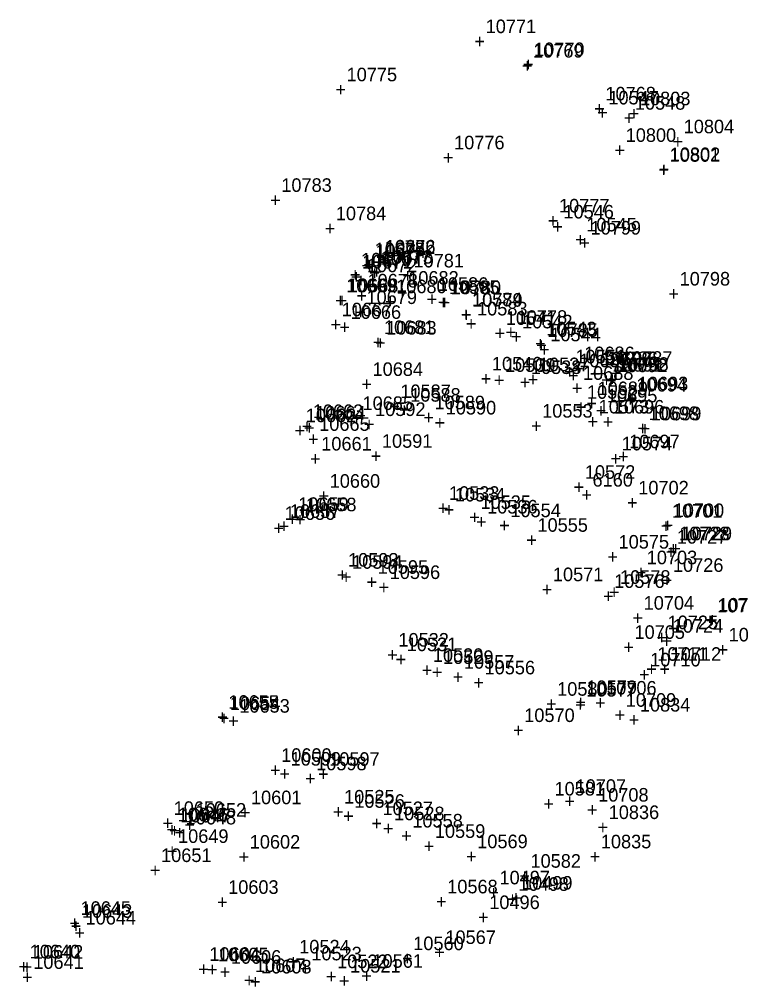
# Model space of a CAD drawing. Extents: x 1136220 to 1137808, y 528804 to 531215.
# Drawn here: x 1136954.1 to 1137087, y 530383.4 to 530561.6 of the extents above; entities that cross this region are included whole.
import ezdxf

# ---------------------------------------------------------------- set-up
doc = ezdxf.new("R2010")
doc.units = 0
for name, color, linetype in [('S_Buildings', 7, 'Continuous'), ('S_Buildings_SillElevation', 7, 'Continuous'), ('S_Curb_Type_1', 7, 'Continuous'), ('S_Curb_Type_3', 7, 'Continuous'), ('S_Drainage_CB', 7, 'Continuous'), ('S_Fencing_ChainLink', 7, 'Continuous'), ('S_Fencing_PostAndRail', 7, 'Continuous'), ('S_Ground_Elevation', 7, 'Continuous'), ('S_Property_IronPipeFound', 7, 'Continuous'), ('S_Property_Light', 7, 'Continuous'), ('S_Railroad_Tracks', 7, 'Continuous'), ('S_RetWall_Top', 7, 'Continuous'), ('S_Roadway_Centerline', 7, 'Continuous'), ('S_Roadway_Drive_Paved', 7, 'Continuous'), ('S_Roadway_Edge_Pavement', 7, 'Continuous'), ('S_Roadway_Sidewalks', 7, 'Continuous'), ('S_Traffic_Post_Conc', 7, 'Continuous'), ('S_Trees_Decid_NonPay', 7, 'Continuous'), ('S_Trees_HedgeLine', 7, 'Continuous'), ('S_Utilities_Pole_Power', 7, 'Continuous')]:
    doc.layers.add(name, color=color, linetype=linetype)

msp = doc.modelspace()

# ---------------------------------------------------------------- texts
at = {"layer": 'S_Buildings'}
for s, p in [('10834', (1137068.47, 530434.07)), ('+', (1137066.41, 530431.32)), ('10835', (1137061.28, 530408.87)), ('+', (1137059.22, 530406.12))]:
    msp.add_text(s, height=2.5, dxfattribs=at).set_placement(p)
at = {"layer": 'S_Buildings_SillElevation'}
for s, p in [('10836', (1137062.73, 530414.27)), ('+', (1137060.67, 530411.52))]:
    msp.add_text(s, height=2.5, dxfattribs=at).set_placement(p)
at = {"layer": 'S_Curb_Type_1'}
for s, p in [('10770', (1137048.98, 530554.79)), ('+', (1137046.92, 530552.04)), ('10802', (1137073.99, 530535.45)), ('+', (1137071.93, 530532.7))]:
    msp.add_text(s, height=2.5, dxfattribs=at).set_placement(p)
at = {"layer": 'S_Curb_Type_3'}
for s, p in [('10674', (1137019.78, 530517.62)), ('10671', (1137017.29, 530515.66)), ('+', (1137017.72, 530514.87)), ('+', (1137015.23, 530512.91)), ('10668', (1137014.68, 530511.31)), ('+', (1137012.62, 530508.56)), ('10667', (1137013.53, 530506.87)), ('+', (1137011.47, 530504.12)), ('10690', (1137061.32, 530497.81)), ('10691', (1137063.41, 530496.67)), ('+', (1137059.26, 530495.06)), ('+', (1137061.35, 530493.92)), ('10694', (1137067.83, 530493.01)), ('+', (1137065.76, 530490.26)), ('10664', (1137008.63, 530487.85)), ('10698', (1137070.07, 530487.76)), ('+', (1137006.57, 530485.1)), ('+', (1137068.01, 530485.01)), ('10657', (1137003.99, 530469.74)), ('10701', (1137074.39, 530469.78)), ('+', (1137001.93, 530466.99)), ('+', (1137072.33, 530467.03)), ('10728', (1137075.7, 530465.61)), ('+', (1137073.64, 530462.86)), ('10731', (1137082.73, 530452.33)), ('+', (1137080.67, 530449.58)), ('10654', (1136992.94, 530434.34)), ('+', (1136990.88, 530431.59)), ('10647', (1136983.81, 530413.65)), ('+', (1136981.75, 530410.9)), ('10643', (1136965.67, 530396.08)), ('+', (1136963.61, 530393.33)), ('10642', (1136956.62, 530388.55)), ('+', (1136954.56, 530385.8))]:
    msp.add_text(s, height=2.5, dxfattribs=at).set_placement(p)
at = {"layer": 'S_Drainage_CB'}
for s, p in [('10771', (1137040.06, 530559.02)), ('+', (1137037.99, 530556.27)), ('10784', (1137012.45, 530524.57)), ('+', (1137010.39, 530521.82)), ('10787', (1137065.17, 530497.92)), ('+', (1137063.11, 530495.17)), ('10662', (1137006.91, 530487.36)), ('10592', (1137019.68, 530488.5)), ('+', (1137004.85, 530484.61)), ('+', (1137017.62, 530485.75)), ('10578', (1137064.82, 530457.59)), ('+', (1137062.76, 530454.84)), ('10650', (1136982.57, 530415.03)), ('+', (1136980.51, 530412.28))]:
    msp.add_text(s, height=2.5, dxfattribs=at).set_placement(p)
at = {"layer": 'S_Fencing_ChainLink'}
for s, p in [('10496', (1137040.73, 530397.69)), ('+', (1137038.67, 530394.94))]:
    msp.add_text(s, height=2.5, dxfattribs=at).set_placement(p)
at = {"layer": 'S_Fencing_PostAndRail'}
for s, p in [('10661', (1137009.77, 530482.14)), ('+', (1137007.71, 530479.39))]:
    msp.add_text(s, height=2.5, dxfattribs=at).set_placement(p)
at = {"layer": 'S_Ground_Elevation'}
for s, p in [('10673', (1137021.04, 530516.58)), ('10672', (1137018.17, 530514.99)), ('+', (1137018.98, 530513.83)), ('10682', (1137025.79, 530512.69)), ('+', (1137016.11, 530512.24)), ('10586', (1137031.23, 530511.55)), ('+', (1137023.73, 530509.94)), ('+', (1137029.17, 530508.8)), ('10583', (1137038.47, 530507.02)), ('10666', (1137015.18, 530506.39)), ('10541', (1137043.77, 530505.29)), ('10683', (1137021.73, 530503.49)), ('+', (1137036.41, 530504.27)), ('+', (1137013.12, 530503.64)), ('+', (1137041.7, 530502.54)), ('10544', (1137051.97, 530502.26)), ('+', (1137019.67, 530500.74)), ('+', (1137049.9, 530499.51)), ('10551', (1137056.6, 530498.19)), ('10540', (1137041.21, 530496.89)), ('10537', (1137049.87, 530496.75)), ('10684', (1137019.22, 530495.88)), ('+', (1137054.54, 530495.44)), ('+', (1137017.16, 530493.13)), ('+', (1137039.15, 530494.14)), ('+', (1137047.81, 530494)), ('10587', (1137024.34, 530491.8)), ('10552', (1137058.73, 530491.67)), ('10685', (1137017.38, 530489.61)), ('+', (1137022.28, 530489.05)), ('10590', (1137032.7, 530488.78)), ('10553', (1137050.47, 530488.2)), ('+', (1137056.67, 530488.92)), ('10573', (1137060.88, 530488.98)), ('10665', (1137009.39, 530485.77)), ('+', (1137015.32, 530486.86)), ('+', (1137030.64, 530486.03)), ('+', (1137058.82, 530486.23)), ('+', (1137048.41, 530485.45)), ('+', (1137007.33, 530483.02)), ('10574', (1137065.12, 530482.17)), ('+', (1137063.06, 530479.42)), ('10572', (1137058.33, 530476.93)), ('10533', (1137033.3, 530473.06)), ('+', (1137056.26, 530474.18)), ('10659', (1137005.52, 530471.02)), ('+', (1137031.24, 530470.31)), ('10536', (1137040.33, 530470.54)), ('10554', (1137044.61, 530469.87)), ('+', (1137003.45, 530468.27)), ('+', (1137038.27, 530467.79)), ('+', (1137042.55, 530467.12)), ('10555', (1137049.6, 530467.18)), ('+', (1137047.54, 530464.43)), ('10575', (1137064.55, 530464.08)), ('10593', (1137014.71, 530460.76)), ('+', (1137062.49, 530461.33)), ('+', (1137012.65, 530458.01)), ('10596', (1137022.38, 530458.48)), ('10571', (1137052.45, 530458.08)), ('+', (1137020.32, 530455.73)), ('10576', (1137063.73, 530456.84)), ('+', (1137050.39, 530455.33)), ('+', (1137061.67, 530454.1)), ('10532', (1137023.98, 530446.03)), ('+', (1137021.91, 530443.28)), ('10529', (1137032.21, 530442.84)), ('10557', (1137036.05, 530441.96)), ('+', (1137030.15, 530440.09)), ('10556', (1137039.86, 530440.92)), ('+', (1137033.99, 530439.21)), ('+', (1137037.8, 530438.17)), ('10577', (1137058.61, 530436.83)), ('10579', (1137058.64, 530437.3)), ('+', (1137056.58, 530434.55)), ('10570', (1137047.17, 530432.14)), ('+', (1137056.55, 530434.08)), ('+', (1137045.11, 530429.39)), ('10600', (1137002.38, 530424.8)), ('10597', (1137011.23, 530424.07)), ('+', (1137000.32, 530422.05)), ('+', (1137009.17, 530421.32)), ('10581', (1137052.74, 530418.6)), ('10525', (1137013.97, 530417.12)), ('+', (1137050.68, 530415.85)), ('10648', (1136984.77, 530413.28)), ('+', (1137011.91, 530414.37)), ('10528', (1137023.19, 530414.05)), ('10558', (1137026.55, 530412.71)), ('+', (1137021.13, 530411.3)), ('10559', (1137030.7, 530410.8)), ('+', (1136982.71, 530410.53)), ('+', (1137024.49, 530409.96)), ('+', (1137028.64, 530408.05)), ('10569', (1137038.51, 530408.9)), ('+', (1137036.45, 530406.15)), ('10582', (1137048.32, 530405.3)), ('+', (1137046.26, 530402.55)), ('10568', (1137032.98, 530400.58)), ('10499', (1137046.76, 530401.27)), ('+', (1137030.92, 530397.83)), ('+', (1137044.7, 530398.52)), ('10644', (1136966.33, 530394.84)), ('+', (1136964.27, 530392.09)), ('10567', (1137032.64, 530391.26)), ('10524', (1137005.71, 530389.51)), ('10560', (1137026.72, 530390.12)), ('10605', (1136990.76, 530388.07)), ('+', (1137030.58, 530388.51)), ('10641', (1136956.71, 530386.67)), ('10608', (1136998.68, 530385.83)), ('+', (1137003.65, 530386.76)), ('10521', (1137015.08, 530385.99)), ('10561', (1137019.2, 530386.88)), ('+', (1137024.66, 530387.37)), ('+', (1136988.7, 530385.32)), ('+', (1136954.65, 530383.92)), ('+', (1136996.62, 530383.08)), ('+', (1137013.02, 530383.24)), ('+', (1137017.14, 530384.13))]:
    msp.add_text(s, height=2.5, dxfattribs=at).set_placement(p)
at = {"layer": 'S_Property_IronPipeFound'}
for s, p in [('6160', (1137059.75, 530475.5)), ('+', (1137057.69, 530472.75))]:
    msp.add_text(s, height=2.5, dxfattribs=at).set_placement(p)
at = {"layer": 'S_Property_Light'}
for s, p in [('10591', (1137020.95, 530482.65)), ('+', (1137018.89, 530479.9)), ('10732', (1137084.83, 530446.98)), ('+', (1137082.77, 530444.23)), ('10580', (1137053.23, 530436.98)), ('+', (1137051.17, 530434.23)), ('10649', (1136983.38, 530409.87)), ('10602', (1136996.59, 530408.82)), ('+', (1136981.32, 530407.12)), ('+', (1136994.53, 530406.07))]:
    msp.add_text(s, height=2.5, dxfattribs=at).set_placement(p)
at = {"layer": 'S_Railroad_Tracks'}
for s, p in [('10547', (1137062.67, 530545.89)), ('10548', (1137067.55, 530544.92)), ('+', (1137060.6, 530543.14)), ('+', (1137065.49, 530542.17)), ('10546', (1137054.39, 530524.88)), ('+', (1137052.33, 530522.13)), ('10545', (1137058.6, 530522.5)), ('+', (1137056.54, 530519.75)), ('10542', (1137046.77, 530504.64)), ('10543', (1137051.22, 530503.36)), ('+', (1137044.71, 530501.89)), ('+', (1137049.16, 530500.61)), ('10539', (1137043.63, 530496.63)), ('10538', (1137048.4, 530496.24)), ('+', (1137041.57, 530493.88)), ('+', (1137046.34, 530493.49)), ('10534', (1137034.39, 530472.76)), ('10535', (1137039.1, 530471.38)), ('+', (1137032.33, 530470.01)), ('+', (1137037.04, 530468.63)), ('10531', (1137025.52, 530445.19)), ('10530', (1137030.33, 530443.21)), ('+', (1137023.46, 530442.44)), ('+', (1137028.27, 530440.46)), ('10526', (1137015.86, 530416.34)), ('10527', (1137021.05, 530414.99)), ('+', (1137013.8, 530413.59)), ('+', (1137018.99, 530412.24)), ('10523', (1137007.94, 530388.24)), ('10522', (1137012.69, 530386.8)), ('+', (1137005.88, 530385.49)), ('+', (1137010.63, 530384.05))]:
    msp.add_text(s, height=2.5, dxfattribs=at).set_placement(p)
at = {"layer": 'S_RetWall_Top'}
for s, p in [('10497', (1137042.61, 530402.24)), ('10498', (1137046.09, 530401.05)), ('+', (1137040.55, 530399.49)), ('+', (1137044.03, 530398.3))]:
    msp.add_text(s, height=2.5, dxfattribs=at).set_placement(p)
at = {"layer": 'S_Roadway_Centerline'}
for s, p in [('10775', (1137014.44, 530550.15)), ('+', (1137012.38, 530547.4)), ('10776', (1137034.24, 530537.62)), ('+', (1137032.18, 530534.87)), ('10777', (1137053.58, 530525.99)), ('+', (1137051.51, 530523.24)), ('10799', (1137059.38, 530521.92)), ('+', (1137057.32, 530519.17)), ('10798', (1137075.8, 530512.53)), ('+', (1137073.73, 530509.78))]:
    msp.add_text(s, height=2.5, dxfattribs=at).set_placement(p)
at = {"layer": 'S_Roadway_Drive_Paved'}
for s, p in [('10675', (1137019.59, 530517.93)), ('10676', (1137021.52, 530518.43)), ('10670', (1137017.1, 530516.04)), ('+', (1137017.53, 530515.18)), ('+', (1137019.46, 530515.68)), ('+', (1137015.04, 530513.29)), ('10669', (1137014.36, 530511.29)), ('+', (1137012.3, 530508.54)), ('10692', (1137064.26, 530496.58)), ('+', (1137062.2, 530493.83)), ('10693', (1137068.09, 530493.23)), ('+', (1137066.02, 530490.48)), ('10663', (1137008.21, 530488.13)), ('10699', (1137070.51, 530487.7)), ('+', (1137006.15, 530485.38)), ('+', (1137068.45, 530484.95)), ('10700', (1137074.71, 530469.89)), ('10656', (1137003.02, 530469.37)), ('+', (1137000.96, 530466.62)), ('+', (1137072.64, 530467.14)), ('10729', (1137076.16, 530465.61)), ('+', (1137074.1, 530462.86)), ('10730', (1137082.91, 530452.48)), ('+', (1137080.85, 530449.73)), ('10655', (1136992.65, 530434.57)), ('+', (1136990.59, 530431.82)), ('10646', (1136983.33, 530413.84)), ('+', (1136981.27, 530411.09)), ('10645', (1136965.4, 530396.62)), ('+', (1136963.34, 530393.87)), ('10640', (1136956.03, 530388.61)), ('+', (1136953.97, 530385.86))]:
    msp.add_text(s, height=2.5, dxfattribs=at).set_placement(p)
at = {"layer": 'S_Roadway_Edge_Pavement'}
for s, p in [('10769', (1137048.8, 530554.52)), ('+', (1137046.74, 530551.77)), ('10768', (1137062.12, 530546.62)), ('+', (1137060.05, 530543.87)), ('10800', (1137065.86, 530538.99)), ('+', (1137063.8, 530536.24)), ('10801', (1137073.95, 530535.33)), ('+', (1137071.89, 530532.58)), ('10783', (1137002.41, 530529.78)), ('+', (1137000.35, 530527.03)), ('10782', (1137021.45, 530518.36)), ('10781', (1137026.76, 530515.87)), ('+', (1137019.39, 530515.61)), ('+', (1137024.7, 530513.12)), ('10780', (1137033.61, 530510.94)), ('+', (1137031.55, 530508.19)), ('10779', (1137037.57, 530508.63)), ('+', (1137035.51, 530505.88)), ('10778', (1137045.78, 530505.47)), ('+', (1137043.72, 530502.72)), ('10785', (1137051.43, 530503.07)), ('+', (1137049.37, 530500.32)), ('10786', (1137062.48, 530497.86)), ('10788', (1137064.48, 530496.82)), ('+', (1137060.42, 530495.11)), ('+', (1137062.42, 530494.07))]:
    msp.add_text(s, height=2.5, dxfattribs=at).set_placement(p)
at = {"layer": 'S_Roadway_Sidewalks'}
for s, p in [('10803', (1137068.49, 530545.73)), ('+', (1137066.43, 530542.98)), ('10804', (1137076.55, 530540.57)), ('+', (1137074.49, 530537.82)), ('10585', (1137033.32, 530510.97)), ('10584', (1137037.54, 530508.71)), ('+', (1137031.26, 530508.22)), ('+', (1137035.48, 530505.96)), ('10686', (1137058.21, 530498.78)), ('10687', (1137057.3, 530497.48)), ('+', (1137056.15, 530496.03)), ('10688', (1137057.99, 530495.16)), ('+', (1137055.24, 530494.73)), ('10588', (1137026.16, 530491.14)), ('+', (1137055.93, 530492.41)), ('10689', (1137060.67, 530492.34)), ('10695', (1137062.4, 530491.01)), ('10589', (1137030.64, 530489.74)), ('+', (1137058.61, 530489.59)), ('+', (1137024.1, 530488.39)), ('+', (1137060.34, 530488.26)), ('10696', (1137063.67, 530488.95)), ('+', (1137028.58, 530486.99)), ('+', (1137061.61, 530486.2)), ('10697', (1137066.51, 530482.56)), ('+', (1137064.44, 530479.81)), ('10702', (1137068.18, 530474.05)), ('+', (1137066.12, 530471.3)), ('10727', (1137075.28, 530464.99)), ('10703', (1137069.74, 530461.2)), ('+', (1137073.22, 530462.24)), ('10594', (1137015.44, 530460.37)), ('10595', (1137020.16, 530459.44)), ('10726', (1137074.57, 530459.79)), ('+', (1137013.38, 530457.62)), ('+', (1137067.68, 530458.45)), ('+', (1137018.1, 530456.69)), ('+', (1137072.51, 530457.04)), ('10704', (1137069.17, 530452.83)), ('+', (1137067.11, 530450.08)), ('10725', (1137073.58, 530449.24)), ('10724', (1137074.52, 530448.59)), ('10705', (1137067.48, 530447.45)), ('+', (1137071.52, 530446.49)), ('+', (1137072.46, 530445.84)), ('+', (1137065.42, 530444.7)), ('10711', (1137071.7, 530443.42)), ('10712', (1137074.15, 530443.41)), ('10710', (1137070.37, 530442.38)), ('+', (1137069.64, 530440.67)), ('+', (1137072.08, 530440.66)), ('+', (1137068.31, 530439.63)), ('10706', (1137062.26, 530437.19)), ('+', (1137060.2, 530434.44)), ('10709', (1137065.87, 530434.95)), ('+', (1137063.81, 530432.2)), ('10599', (1137004.12, 530424.11)), ('10598', (1137008.83, 530423.25)), ('+', (1137002.06, 530421.36)), ('+', (1137006.77, 530420.5)), ('10707', (1137056.63, 530419.09)), ('10708', (1137060.78, 530417.48)), ('+', (1137054.57, 530416.34)), ('+', (1137058.72, 530414.73)), ('10606', (1136993.1, 530387.62)), ('10607', (1136997.57, 530386.09)), ('+', (1136991.04, 530384.87)), ('+', (1136995.51, 530383.34))]:
    msp.add_text(s, height=2.5, dxfattribs=at).set_placement(p)
at = {"layer": 'S_Traffic_Post_Conc'}
for s, p in [('10677', (1137020.67, 530516.37)), ('+', (1137018.61, 530513.62)), ('10678', (1137018.28, 530512.18)), ('10680', (1137023.57, 530511.12)), ('+', (1137016.22, 530509.43)), ('10679', (1137018.1, 530509.13)), ('+', (1137021.51, 530508.37)), ('+', (1137016.04, 530506.38))]:
    msp.add_text(s, height=2.5, dxfattribs=at).set_placement(p)
at = {"layer": 'S_Trees_Decid_NonPay'}
for s, p in [('10660', (1137011.32, 530475.29)), ('+', (1137009.26, 530472.54)), ('10603', (1136992.61, 530400.49)), ('+', (1136990.55, 530397.74)), ('10604', (1136989.16, 530388.15)), ('+', (1136987.1, 530385.4))]:
    msp.add_text(s, height=2.5, dxfattribs=at).set_placement(p)
at = {"layer": 'S_Trees_HedgeLine'}
for s, p in [('10658', (1137006.96, 530470.95)), ('+', (1137004.9, 530468.2)), ('10653', (1136994.67, 530433.86)), ('+', (1136992.61, 530431.11)), ('10652', (1136986.62, 530414.7)), ('+', (1136984.55, 530411.95)), ('10651', (1136980.25, 530406.35)), ('+', (1136978.19, 530403.6))]:
    msp.add_text(s, height=2.5, dxfattribs=at).set_placement(p)
at = {"layer": 'S_Utilities_Pole_Power'}
for s, p in [('10681', (1137021.32, 530503.61)), ('+', (1137019.26, 530500.86)), ('10601', (1136996.82, 530417)), ('+', (1136994.76, 530414.25))]:
    msp.add_text(s, height=2.5, dxfattribs=at).set_placement(p)

doc.saveas('drawing.dxf')
